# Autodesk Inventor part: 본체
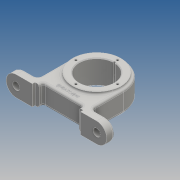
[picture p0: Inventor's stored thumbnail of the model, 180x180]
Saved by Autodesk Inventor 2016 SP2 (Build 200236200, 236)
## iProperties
Created: 2019-05
Part Number: 본체
Material: Generic
Document SubType Name: Modeling
Designer: EZ
Density: 1 g/cm^3
Appearance: Default
Author: EZ
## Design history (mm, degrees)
sketch "스케치1"
  geometry: L1 (60, 0)-(-60, 0); L2 (60, 15)-(-60, 15); L3 (-60, -15)-(60, -15); A1 r 15 centre (60, 0) between (60, -15) and (60, 15); A2 r 15 centre (-60, 0) between (-60, 15) and (-60, -15); 2 further points
  constraints: 8 end point, 4 point on circle, 4 tangent, 2 centre point, 1 coincident, 1 horizontal, 1 midpoint, 1 parallel
  dimensions: "d0" = 120 distance of L1.start L1.end; "d1" = 30 diameter of A2
extrude "돌출1" new body sketch "스케치1" distance "d2" = 12; taper "d3" = 0 deg
sketch "스케치2"
  geometry: C1 r 9 at (-60, 0); C2 r 9 at (60, 0); A1 r 15 centre (-60, 0) between (-60, 15) and (-60, -15) reference; A2 r 15 centre (60, 0) between (60, -15) and (60, 15) reference; 1 further point
  constraints: 2 centre point, 2 coincident
  dimensions: "d4" = 18 diameter of C1; "d5" = 18 diameter of C2
extrude "돌출2" join sketch "스케치2" distance "d6" = 3; taper "d7" = 0 deg
sketch "스케치3"
  geometry: L1 (-40, 15)-(40, 15); L2 (40, 15)-(40, -15); L3 (40, -15)-(-40, -15); L4 (-40, -15)-(-40, 15); L5 (-40, 15)-(40, -15); L6 (40, 15)-(-40, -15); 1 further point
  constraints: 12 end point, 2 midpoint, 2 parallel, 1 horizontal, 1 perpendicular
  dimensions: "d8" = 80 distance of L2.end L3.end; "d9" = 30 distance of L1.end L2.end
extrude "돌출3" join sketch "스케치3" distance "d10" = 88; taper "d11" = 0 deg
fillet "모깎기1" dims "d12" = 40
sketch "스케치4"
  geometry: L1 (120, 0)-(0, 0) reference; L2 (24, 0)-(24, 4); L3 (24, 4)-(30, 4); L4 (30, 4)-(30, 10); L5 (30, 10)-(90, 10); L6 (90, 10)-(90, 4); L7 (90, 4)-(96, 4); L8 (96, 4)-(96, 0); 1 further point
  constraints: 14 end point, 5 perpendicular, 4 point on line, 1 collinear, 1 vertical
  dimensions: "d13" = 72 distance of L8.end L2.start; "d14" = 60 distance of L6.end L3.end; "d15" = 4 vertical distance of L2.start L3.end; "d16" = 10 distance from line of L5 L2.start; "d17" = 36 distance of point (60, 0) L2.start
extrude "돌출4" cut sketch "스케치4" stored distance "d18" = 88; taper "d19" = 0 deg
sketch "스케치6"
  geometry: C1 r 36 at (0, 60); A1 r 40 centre (0, 60) between (40, 60) and (-40, 60) reference; 1 further point
  constraints: 1 centre point, 1 coincident
  dimensions: "d21" = 72 diameter of C1
extrude "돌출5" join sketch "스케치6" stored distance "d22" = 36; taper "d23" = 0 deg
hole "구멍1" diameter "d26" = 52; stored, may be unused: countersink angle "d30" = 90 deg, drill point angle "d32" = 118 deg; dims "d24" = 10, "d25" = 10, "d27" = 6, "d28" = 4, "d29" = 2, "d31" = 8
chamfer "모따기1" distance "d33" = 1; stored, may be unused: second distance "d34" = 2, angle "d35" = 45 deg
sketch "스케치7"
  geometry: C1 r 1.5 at (0, 26); 2 further points
  constraints: 2 vertical alignment, 1 centre point, 1 other
  dimensions: "d36" = 3 diameter of C1
extrude "돌출6" cut sketch "스케치7" stored distance "d37" = 35; taper "d38" = 0 deg
sketch "스케치8"
  geometry: C1 r 36 at (0, 0) reference; C2 r 26 at (0, 0); A1 r 26 centre (0, 0) between (-1.499, 25.957) and (1.499, 25.957) reference; 5 further points
  constraints: 1 centre point, 1 coincident, 1 vertical alignment, 5 other
  dimensions: "d41" = 360 deg dimension on C1.centre point (0, 31) (derived); "d43" = 62 distance of point (31, 0) point (-31, 0); "d87" = 52 diameter of C2
hole "구멍2" sketch "스케치8" at (0, 31), (-31, 0), (0, -31), (31, 0) diameter "d44" = 3.242; stored, may be unused: countersink angle "d48" = 90 deg, drill point angle "d50" = 118 deg; dims "d45" = 6, "d46" = 4, "d47" = 2, "d49" = 8
node "작업 평면1"
sketch "스케치9"
  geometry: 2 further points
  constraints: 1 coincident
hole "구멍3" sketch "스케치9" at (0, 0) diameter "d52" = 4.917; stored, may be unused: countersink angle "d56" = 90 deg, drill point angle "d58" = 118 deg; dims "d53" = 8, "d54" = 7, "d55" = 1, "d57" = 10
sketch "스케치11"
  geometry: L1 (88.523, 0)-(90, -2.459) reference; L2 (88.523, 0)-(90, 2.459) reference; L3 (87.5, 18)-(87.5, -18) reference; L4 (88.523, 0)-(87.5, 0); L5 (89.124, 1)-(87.5, 1); 1 further point
  constraints: 4 end point, 2 point on line, 1 midpoint, 1 perpendicular
  dimensions: "d59" = 2 diameter of L5 L4
revolve "회전1" sketch "스케치11" stored, may be unused: angle "d60" = 90 deg
sketch "스케치13"
  geometry: L1 (-30, 10)-(-90, 10) reference; 2 further points
  constraints: 1 vertical alignment, 1 other
  dimensions: "d61" = 7 distance from line of L1 point (-60, 17)
feature "엠보싱1" sketch "스케치13" dims "d0" = 120, "d1" = 30, "d8" = 80, "d9" = 30, "d62" = 0.5, "d63" = 0
hole "구멍4" diameter "d66" = 11; stored, may be unused: countersink angle "d70" = 90 deg, drill point angle "d72" = 118 deg; dims "d64" = 10, "d65" = 10, "d67" = 8, "d68" = 7, "d69" = 1, "d71" = 10
hole "구멍5" diameter "d75" = 11; stored, may be unused: countersink angle "d79" = 90 deg, drill point angle "d81" = 118 deg; dims "d73" = 10, "d74" = 10, "d76" = 8, "d77" = 7, "d78" = 1, "d80" = 10
fillet "모깎기2" dims "d82" = 6
fillet "모깎기3" dims "d83" = 3
fillet "모깎기4" dims "d84" = 3
fillet "모깎기5" dims "d85" = 3
fillet "모깎기6" dims "d86" = 3
node "솔리드1"
mirror "대칭1"
